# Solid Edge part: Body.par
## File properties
Author: jmrobins
Template: ANSIMM.PAR
Last saved by: rkriggs
Revision: 71
Application: Solid Edge
Density: 0.00000692 kg/mm^3
Accuracy: 0.99
Material: Iron, grey cast type 20
Face Style: Steel
Fill Style: ANSI31(Iron)
Virtual Style: Cast iron
Coef. of Thermal Exp: 1.1e-05
Thermal Conductivity: 48.0
Specific Heat: 544.0
Modulus of Elasticity: 66190000000.0
Poission's Ratio: 0.29
Yield Stress: 572264831.0
Ultimate Stress: 137895140.0
Elongation: 0.0
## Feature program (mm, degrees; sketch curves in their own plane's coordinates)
pattern "unnamed Pattern 1"
pattern "unnamed Pattern 2"
pattern "unnamed Pattern 3"
pattern "unnamed Pattern 4"
pattern "unnamed Pattern 5"
pattern "unnamed Pattern 6"
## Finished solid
Body 1: solid body, 117 faces, 268 edges, 140 vertices.
  Faces by surface: cylinder 57, plane 30, torus 22, sphere 4, blend 2, cone 2
  Edges by curve: circle 139, line 112, intersection 17
Bounding box of the edges (mm; curved faces can reach further): 90.000 x 70.000 x 128.000, from (-45, -35, -45) to (45, 35, 83).
Cylindrical faces by radius (mm): R2 x14, R3.4585 x12, R4 x10, R7.5 x1, R10 x13, R16 x2, R30 x1, R32.5 x2, R35 x2
Conical faces (half-angle, radius in mm at the cone's reference point): 45 deg R33.5 x2
Toroidal faces (ring radius, tube radius in mm): R8 r2 x12, R8 r4 x4, R20 r4 x2, R39 r4 x4
Spherical faces by radius (mm): R4 x4
Planar faces by outward normal: +x 6, +y 4, +z 5, -x 5, -y 4, -z 4, oblique 2
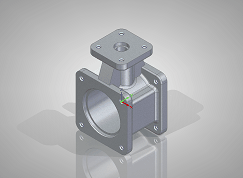
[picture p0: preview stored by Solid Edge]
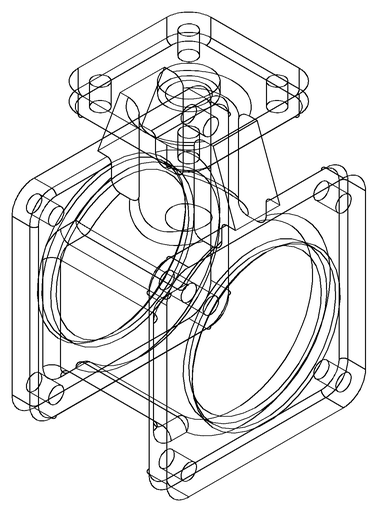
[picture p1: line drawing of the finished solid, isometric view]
